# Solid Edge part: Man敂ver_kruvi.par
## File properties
Author: Olev
Template: Normal.par
Last saved by: Olev
Revision: 31
Application: Solid Edge
Accuracy: 0,990
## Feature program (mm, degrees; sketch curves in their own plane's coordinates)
sketch for "unnamed Protrusion 1" plane through (0, 0, 0) normal (0, -1, 0) x-axis (1, 0, 0)
  circle centre (0, 0) radius 0.85
extrude "unnamed Protrusion 1" add finite 1.5 symmetric
swept protrusion "unnamed SweptProtrusion 1"
sketch for "ExtrudedCutout_3" plane through (-1.3122, 0, 3.6809) normal (0, -1, 0) x-axis (0.595418, 0, 0.803416)
extrude "ExtrudedCutout_3" cut finite 3.6754 symmetric
pattern "unnamed Pattern 1" of "unnamed SweptProtrusion 1", "ExtrudedCutout_3"
swept protrusion "unnamed SweptProtrusion 2"
extrude "unnamed Cutout 1" cut finite 3.6754 symmetric
swept protrusion "unnamed SweptProtrusion 3"
extrude "unnamed Cutout 2" cut finite 3.6754 symmetric
swept protrusion "unnamed SweptProtrusion 4"
extrude "unnamed Cutout 3" cut finite 3.6754 symmetric
swept protrusion "unnamed SweptProtrusion 5"
extrude "unnamed Cutout 4" cut finite 3.6754 symmetric
chamfer "unnamed Chamfer 1"
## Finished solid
Body 1: solid body, 20 faces, 34 edges, 20 vertices.
  Faces by surface: spline 10, swept 5, cone 2, plane 2, cylinder 1
  Edges by curve: intersection 20, spline 10, circle 4
Bounding box of the edges (mm; curved faces can reach further): 6.978 x 1.500 x 6.727, from (-3.5076, -0.75, -3.0713) to (3.4706, 0.75, 3.6553).
Cylindrical faces by radius (mm): R0.85 x1
Conical faces (half-angle, radius in mm at the cone's reference point): 45 deg R0.75 x1, 45 deg R0.85 x1
Planar faces by outward normal: +y 1, -y 1
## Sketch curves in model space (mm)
line (-0.6755, 0.0625, 4.5401) -> (-0.7119, 0.0748, 4.491)
spline (-0.6755, 0.0625, 4.5401) -> (-1.8062, -0.3044, 3.0144) -> (-0.7119, 0.0748, 4.491)
spline (0, 0, 0) -> (-0.1278, 0, 1.6501) -> (-1.3122, 0, 3.6809)
line (0.3262, 0.6079, 0) -> (0.3586, 0.6438, 0)
spline (0.3586, 0.6438, 0) -> (-0.1662, -0.5699, 0) -> (0.3262, 0.6079, 0)
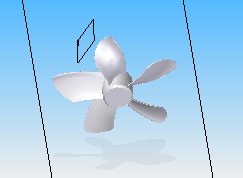
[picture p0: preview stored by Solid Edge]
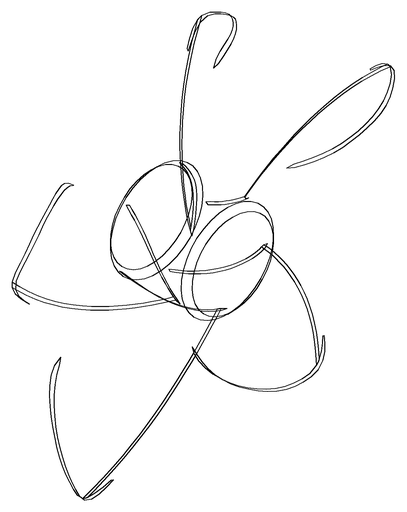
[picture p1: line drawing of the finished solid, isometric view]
